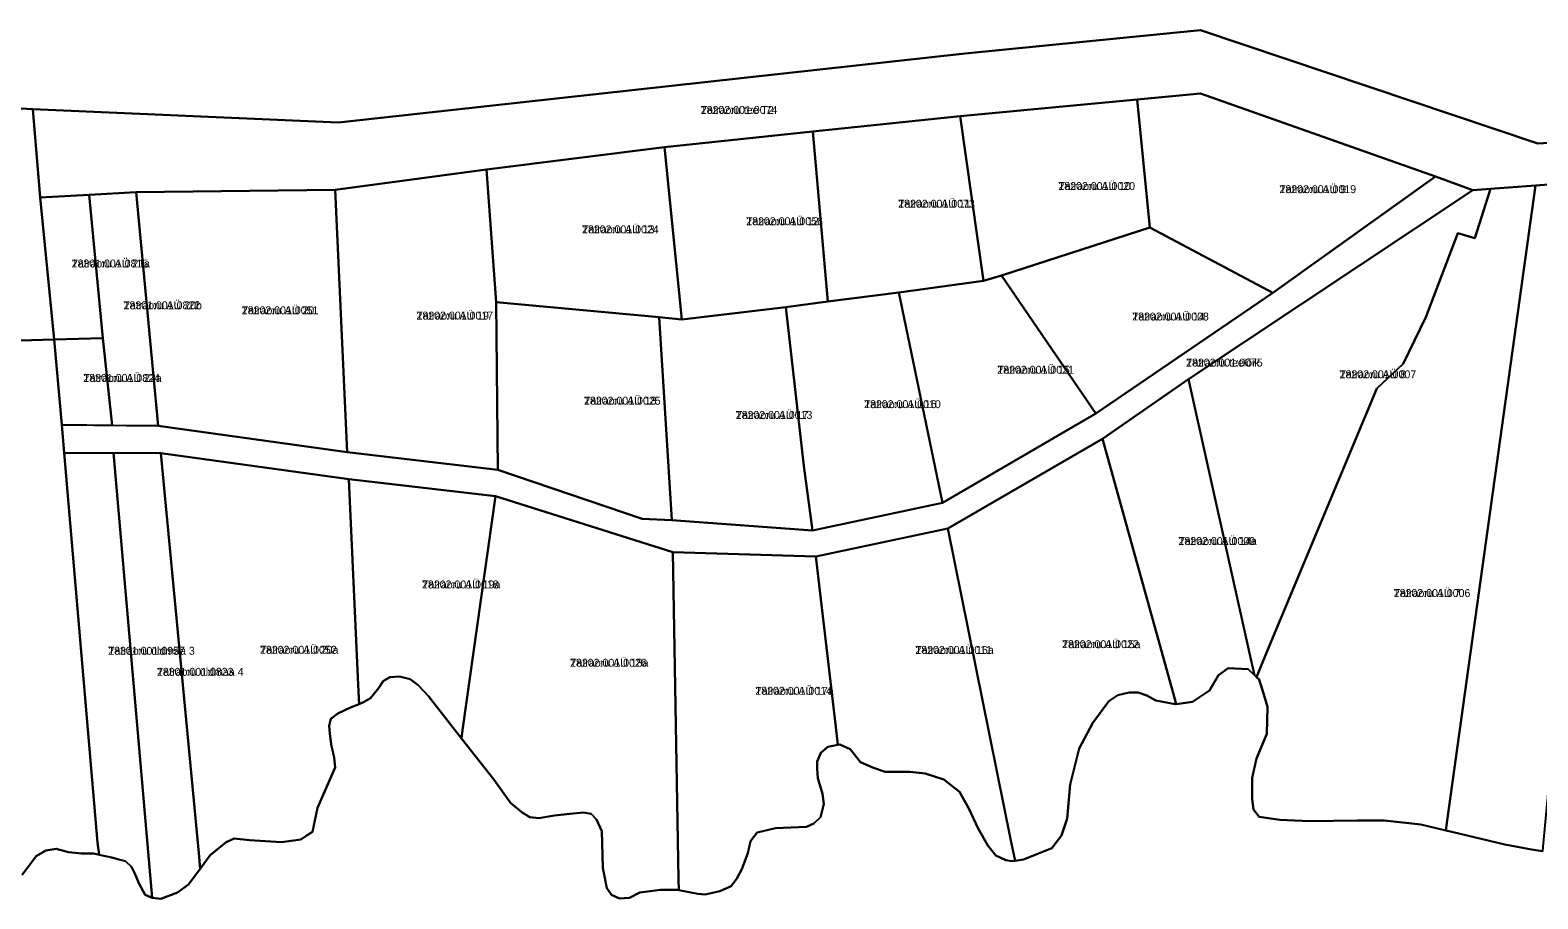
# Model space of a CAD drawing. Extents: x 647845 to 668483, y 6445298 to 6473683.
# Drawn here: x 655354.6 to 655639.8, y 6459755.9 to 6459920.2 of the extents above; entities that cross this region are included whole.
import ezdxf

# ---------------------------------------------------------------- set-up
doc = ezdxf.new("R2010")
doc.units = 0
for name, color, linetype in [('L_AADRESS', 7, 'Continuous'), ('PIIR', 7, 'Continuous'), ('TUNNUS', 7, 'Continuous')]:
    doc.layers.add(name, color=color, linetype=linetype)

msp = doc.modelspace()

# ---------------------------------------------------------------- linework, layer by layer
at = {"layer": 'PIIR'}
for points in [[(655768.57, 6459906.32), (655639.81, 6459898.78), (655575.98, 6459920.24), (655531.44, 6459915.82), (655412.9, 6459902.78), (655355.04, 6459905.27), (655320.6, 6459907.21)], [(655654.46, 6459891.98), (655639.35, 6459890.87), (655630.86, 6459890.25), (655627.53, 6459889.99), (655620.48, 6459892.55), (655576, 6459908.29), (655564.03, 6459907.15), (655530.51, 6459903.96), (655502.65, 6459901.05), (655474.56, 6459898.1), (655440.88, 6459893.86), (655412.27, 6459890.06), (655374.61, 6459889.57), (655365.71, 6459889.08), (655356.48, 6459888.57), (655355.04, 6459905.27), (655412.9, 6459902.78), (655531.44, 6459915.82), (655575.98, 6459920.24), (655639.81, 6459898.78), (655768.57, 6459906.32)], [(655311.68, 6459860.34), (655359.12, 6459861.71), (655360.53, 6459845.6), (655360.99, 6459840.29), (655367.3, 6459766.59), (655367.63, 6459764.27), (655366.6, 6459764.5), (655364.26, 6459764.49), (655361.82, 6459764.75), (655359.5, 6459765.35), (655357.54, 6459765.06), (655355.71, 6459764), (655353.02, 6459760.45)], [(655353.02, 6459760.45), (655355.71, 6459764), (655357.54, 6459765.06), (655359.5, 6459765.35), (655361.82, 6459764.75), (655364.26, 6459764.49), (655366.6, 6459764.5), (655367.63, 6459764.27), (655370.02, 6459763.77), (655371.36, 6459763.38), (655372.59, 6459763.03), (655373.73, 6459761.95), (655374.3, 6459760.83), (655375.21, 6459758.73), (655376.31, 6459756.65), (655377.65, 6459756.08), (655379.25, 6459755.92), (655382.43, 6459757.14), (655384.51, 6459758.61), (655386.72, 6459761.6), (655388.62, 6459764.18), (655391.67, 6459766.62), (655393.18, 6459767.34), (655396.06, 6459767.05), (655402.11, 6459766.64), (655405.77, 6459767.14), (655406.96, 6459767.94), (655407.97, 6459768.61), (655408.95, 6459773.13), (655410.66, 6459777.17), (655412.24, 6459780.76), (655412.08, 6459782.67), (655411.51, 6459785.12), (655411.23, 6459787.22), (655411.15, 6459788.67), (655411.44, 6459789.97), (655412.74, 6459790.99), (655415.18, 6459792.1), (655416.81, 6459792.76), (655417.63, 6459793.1), (655418.94, 6459793.9), (655420.5, 6459795.85), (655421.37, 6459797.12), (655422.6, 6459797.84), (655424.42, 6459798), (655426.47, 6459797.48), (655427.96, 6459796.37), (655429.91, 6459794.27), (655436.16, 6459786.28), (655442.26, 6459778.5), (655445.44, 6459774.1), (655447.65, 6459772.26), (655449.1, 6459771.34), (655450.82, 6459771.17), (655453.76, 6459771.66), (655456.69, 6459772.03), (655459.26, 6459772.28), (655460.68, 6459772.01), (655461.71, 6459770.93), (655462.69, 6459768.73), (655462.93, 6459761.76), (655463.66, 6459757.97), (655464.53, 6459756.66), (655466.05, 6459756), (655467.95, 6459756.14), (655469.9, 6459757.12), (655473.82, 6459757.61), (655477, 6459757.61), (655477.27, 6459757.56), (655480.86, 6459756.87), (655482.25, 6459756.76), (655485.03, 6459757.34), (655487.18, 6459758.34), (655488.27, 6459759.79), (655489.23, 6459761.53), (655490.33, 6459764.59), (655490.82, 6459766.8), (655492.09, 6459768.46), (655495.56, 6459769.26), (655501.42, 6459769.53), (655502.81, 6459770.18), (655504.09, 6459771.4), (655504.7, 6459773.85), (655504.46, 6459775.8), (655503.6, 6459778.74), (655503.44, 6459780.51), (655503.48, 6459781.93), (655504.15, 6459783.56), (655505.5, 6459784.67), (655507.38, 6459785.04), (655507.73, 6459785.11), (655509.72, 6459784.25), (655511.67, 6459781.8), (655514.12, 6459780.7), (655516.32, 6459779.97), (655520.97, 6459779.97), (655523.9, 6459779.61), (655527.45, 6459778.51), (655530.39, 6459776.19), (655532.1, 6459773.13), (655533.93, 6459769.22), (655535.77, 6459766.04), (655537.24, 6459764.09), (655539.19, 6459763.23), (655540.27, 6459763.02), (655540.9, 6459763.12), (655542.51, 6459763.39), (655547.85, 6459765.52), (655549.71, 6459767.93), (655550.78, 6459771.13), (655551.31, 6459777.54), (655553.06, 6459784.38), (655555.6, 6459789.22), (655558.62, 6459793.31), (655560.36, 6459794.47), (655562.51, 6459794.97), (655564.22, 6459794.97), (655565.84, 6459794.36), (655567.52, 6459793.45), (655571.19, 6459792.72), (655571.41, 6459792.75), (655574.49, 6459793.21), (655577.67, 6459795.3), (655579.38, 6459798.23), (655581.22, 6459799.58), (655585.01, 6459799.34), (655586.18, 6459798.24), (655586.56, 6459797.88), (655587.09, 6459797.38), (655587.96, 6459794.57), (655588.68, 6459792.25), (655588.56, 6459787.11), (655586.6, 6459782.46), (655585.75, 6459778.79), (655585.75, 6459774.75), (655586.01, 6459772.81), (655587.09, 6459771.45), (655591.01, 6459770.84), (655596.63, 6459770.6), (655605.68, 6459770.73), (655610.82, 6459770.73), (655617.67, 6459770.01), (655622.42, 6459768.87), (655623.78, 6459768.54), (655633.57, 6459766.23), (655638.64, 6459765.23), (655640.72, 6459764.95)]]:
    msp.add_lwpolyline(points, dxfattribs=at)
for points in [[(655356.48, 6459888.57), (655359.12, 6459861.71), (655311.68, 6459860.34), (655309.48, 6459884.36), (655283.02, 6459882.57), (655286.95, 6459909.12), (655320.6, 6459907.21), (655355.04, 6459905.27)], [(655566.42, 6459882.91), (655538.32, 6459873.83), (655534.92, 6459872.85), (655530.51, 6459903.96), (655564.03, 6459907.15)], [(655589.65, 6459870.53), (655566.42, 6459882.91), (655564.03, 6459907.15), (655576, 6459908.29), (655620.48, 6459892.55)], [(655530.51, 6459903.96), (655534.92, 6459872.85), (655518.92, 6459870.61), (655505.51, 6459868.92), (655502.65, 6459901.05)], [(655502.65, 6459901.05), (655505.51, 6459868.92), (655497.53, 6459867.87), (655477.84, 6459865.52), (655474.56, 6459898.1)], [(655474.56, 6459898.1), (655477.84, 6459865.52), (655473.54, 6459865.92), (655442.72, 6459868.8), (655440.88, 6459893.86)], [(655360.56, 6459845.6), (655378.76, 6459845.37), (655414.56, 6459840.41), (655443.03, 6459837.1), (655470.38, 6459827.8), (655475.98, 6459827.52), (655502.56, 6459825.62), (655527.17, 6459830.85), (655556.16, 6459847.73), (655589.65, 6459870.53), (655620.48, 6459892.55), (655627.53, 6459889.99), (655573.74, 6459854.22), (655557.45, 6459842.92), (655528.19, 6459825.96), (655503.19, 6459820.66), (655476.13, 6459821.49), (655442.58, 6459832.09), (655414.83, 6459835.32), (655379.28, 6459840.23), (655360.99, 6459840.29)], [(655440.88, 6459893.86), (655442.72, 6459868.8), (655443.03, 6459837.1), (655414.56, 6459840.41), (655412.27, 6459890.06)], [(655365.71, 6459889.08), (655374.61, 6459889.57), (655378.76, 6459845.37), (655370.09, 6459845.48), (655368.32, 6459861.95)], [(655412.27, 6459890.06), (655414.56, 6459840.41), (655378.76, 6459845.37), (655374.61, 6459889.57)], [(655627.88, 6459880.88), (655624.67, 6459881.81), (655618.62, 6459865.96), (655614.31, 6459857.14), (655609.35, 6459852.46), (655588.74, 6459803.1), (655586.56, 6459797.88), (655586.18, 6459798.24), (655585.26, 6459802.38), (655573.74, 6459854.22), (655627.53, 6459889.99), (655630.86, 6459890.25)], [(655622.68, 6459770.73), (655622.42, 6459768.87), (655617.67, 6459770.01), (655610.82, 6459770.73), (655605.68, 6459770.73), (655596.63, 6459770.6), (655591.01, 6459770.84), (655587.09, 6459771.45), (655586.01, 6459772.81), (655585.75, 6459774.75), (655585.75, 6459778.79), (655586.6, 6459782.46), (655588.56, 6459787.11), (655588.68, 6459792.25), (655587.96, 6459794.57), (655587.09, 6459797.38), (655586.56, 6459797.88), (655588.74, 6459803.1), (655609.35, 6459852.46), (655614.31, 6459857.14), (655618.62, 6459865.96), (655624.67, 6459881.81), (655627.88, 6459880.88), (655630.86, 6459890.25), (655639.35, 6459890.87)], [(655658.06, 6459850.82), (655653.33, 6459801.58), (655644.06, 6459800.68), (655640.79, 6459765.73), (655640.72, 6459764.95), (655638.64, 6459765.23), (655633.57, 6459766.23), (655623.78, 6459768.54), (655622.42, 6459768.87), (655622.68, 6459770.73), (655639.35, 6459890.87), (655654.46, 6459891.98)], [(655356.48, 6459888.57), (655365.71, 6459889.08), (655368.32, 6459861.95), (655359.12, 6459861.71)], [(655556.16, 6459847.73), (655538.32, 6459873.83), (655566.42, 6459882.91), (655589.65, 6459870.53)], [(655538.32, 6459873.83), (655556.16, 6459847.73), (655527.17, 6459830.85), (655518.92, 6459870.61), (655534.92, 6459872.85)], [(655502.56, 6459825.62), (655500.95, 6459837.8), (655497.53, 6459867.87), (655505.51, 6459868.92), (655518.92, 6459870.61), (655527.17, 6459830.85)], [(655473.54, 6459865.92), (655475.98, 6459827.52), (655470.38, 6459827.8), (655443.03, 6459837.1), (655442.72, 6459868.8)], [(655475.98, 6459827.52), (655473.54, 6459865.92), (655477.84, 6459865.52), (655497.53, 6459867.87), (655500.95, 6459837.8), (655502.56, 6459825.62)], [(655359.12, 6459861.71), (655368.32, 6459861.95), (655370.09, 6459845.48), (655360.56, 6459845.6)], [(655585.26, 6459802.38), (655586.18, 6459798.24), (655585.01, 6459799.34), (655581.22, 6459799.58), (655579.38, 6459798.23), (655577.67, 6459795.3), (655574.49, 6459793.21), (655571.41, 6459792.75), (655570.88, 6459794.65), (655557.45, 6459842.92), (655573.74, 6459854.22)], [(655557.45, 6459842.92), (655570.88, 6459794.65), (655571.41, 6459792.75), (655571.19, 6459792.72), (655567.52, 6459793.45), (655565.84, 6459794.36), (655564.22, 6459794.97), (655562.51, 6459794.97), (655560.36, 6459794.47), (655558.62, 6459793.31), (655555.6, 6459789.22), (655553.06, 6459784.38), (655551.31, 6459777.54), (655550.78, 6459771.13), (655549.71, 6459767.93), (655547.85, 6459765.52), (655542.51, 6459763.39), (655540.9, 6459763.12), (655540.06, 6459767.28), (655528.19, 6459825.96)], [(655360.99, 6459840.29), (655370.35, 6459840.26), (655377.65, 6459756.08), (655376.31, 6459756.65), (655375.21, 6459758.73), (655374.3, 6459760.83), (655373.73, 6459761.95), (655372.59, 6459763.03), (655371.36, 6459763.38), (655370.02, 6459763.77), (655367.63, 6459764.27), (655367.3, 6459766.59)], [(655379.28, 6459840.23), (655386.44, 6459764.54), (655386.72, 6459761.6), (655384.51, 6459758.61), (655382.43, 6459757.14), (655379.25, 6459755.92), (655377.65, 6459756.08), (655370.35, 6459840.26)], [(655416.64, 6459796.42), (655416.81, 6459792.76), (655415.18, 6459792.1), (655412.74, 6459790.99), (655411.44, 6459789.97), (655411.15, 6459788.67), (655411.23, 6459787.22), (655411.51, 6459785.12), (655412.08, 6459782.67), (655412.24, 6459780.76), (655410.66, 6459777.17), (655408.95, 6459773.13), (655407.97, 6459768.61), (655406.96, 6459767.94), (655405.77, 6459767.14), (655402.11, 6459766.64), (655396.06, 6459767.05), (655393.18, 6459767.34), (655391.67, 6459766.62), (655388.62, 6459764.18), (655386.72, 6459761.6), (655386.44, 6459764.54), (655379.28, 6459840.23), (655414.83, 6459835.32)], [(655436.38, 6459787.84), (655436.16, 6459786.28), (655429.91, 6459794.27), (655427.96, 6459796.37), (655426.47, 6459797.48), (655424.42, 6459798), (655422.6, 6459797.84), (655421.37, 6459797.12), (655420.5, 6459795.85), (655418.94, 6459793.9), (655417.63, 6459793.1), (655416.81, 6459792.76), (655416.64, 6459796.42), (655414.83, 6459835.32), (655442.58, 6459832.09)], [(655476.13, 6459821.49), (655477.23, 6459759.66), (655477.27, 6459757.56), (655477, 6459757.61), (655473.82, 6459757.61), (655469.9, 6459757.12), (655467.95, 6459756.14), (655466.05, 6459756), (655464.53, 6459756.66), (655463.66, 6459757.97), (655462.93, 6459761.76), (655462.69, 6459768.73), (655461.71, 6459770.93), (655460.68, 6459772.01), (655459.26, 6459772.28), (655456.69, 6459772.03), (655453.76, 6459771.66), (655450.82, 6459771.17), (655449.1, 6459771.34), (655447.65, 6459772.26), (655445.44, 6459774.1), (655442.26, 6459778.5), (655436.16, 6459786.28), (655436.38, 6459787.84), (655442.58, 6459832.09)], [(655528.19, 6459825.96), (655540.06, 6459767.28), (655540.9, 6459763.12), (655540.27, 6459763.02), (655539.19, 6459763.23), (655537.24, 6459764.09), (655535.77, 6459766.04), (655533.93, 6459769.22), (655532.1, 6459773.13), (655530.39, 6459776.19), (655527.45, 6459778.51), (655523.9, 6459779.61), (655520.97, 6459779.97), (655516.32, 6459779.97), (655514.12, 6459780.7), (655511.67, 6459781.8), (655509.72, 6459784.25), (655507.73, 6459785.11), (655507.38, 6459785.04), (655506.91, 6459788.95), (655503.19, 6459820.66)], [(655506.91, 6459788.95), (655507.38, 6459785.04), (655505.5, 6459784.67), (655504.15, 6459783.56), (655503.48, 6459781.93), (655503.44, 6459780.51), (655503.6, 6459778.74), (655504.46, 6459775.8), (655504.7, 6459773.85), (655504.09, 6459771.4), (655502.81, 6459770.18), (655501.42, 6459769.53), (655495.56, 6459769.26), (655492.09, 6459768.46), (655490.82, 6459766.8), (655490.33, 6459764.59), (655489.23, 6459761.53), (655488.27, 6459759.79), (655487.18, 6459758.34), (655485.03, 6459757.34), (655482.25, 6459756.76), (655480.86, 6459756.87), (655477.27, 6459757.56), (655477.23, 6459759.66), (655476.13, 6459821.49), (655503.19, 6459820.66)]]:
    msp.add_lwpolyline(points, close=True, dxfattribs=at)

# ---------------------------------------------------------------- texts
at = {"layer": 'L_AADRESS'}
for s, p in [('Tatraoru tee T2', (655481.43, 6459904.4)), ('Tatraoru AÜ 10', (655549.1, 6459890)), ('Tatraoru AÜ 9', (655590.93, 6459889.41)), ('Tatraoru AÜ 11', (655518.79, 6459886.66)), ('Tatraoru AÜ 12', (655490.04, 6459883.35)), ('Tatraoru AÜ 13', (655458.98, 6459881.81)), ('Tatraoru AÜ 21a', (655362.4, 6459875.35)), ('Tatraoru AÜ 20b', (655372.23, 6459867.45)), ('Tatraoru AÜ 20', (655394.59, 6459866.5)), ('Tatraoru AÜ 19', (655427.65, 6459865.5)), ('Tatraoru AÜ 14', (655563.07, 6459865.32)), ('Tatraoru teelõik', (655573.26, 6459856.61)), ('Tatraoru AÜ 22a', (655364.61, 6459853.7)), ('Tatraoru AÜ 15', (655537.54, 6459855.25)), ('Tatraoru AÜ 8', (655602.3, 6459854.39)), ('Tatraoru AÜ 18', (655459.35, 6459849.4)), ('Tatraoru AÜ 16', (655512.35, 6459848.74)), ('Tatraoru AÜ 17', (655488.05, 6459846.7)), ('Tatraoru AÜ 14a', (655571.82, 6459822.85)), ('Tatraoru AÜ 19a', (655428.7, 6459814.64)), ('Tatraoru AÜ 7', (655612.55, 6459813.01)), ('Tatraoru AÜ 20a', (655398.05, 6459802.28)), ('Tatraoru AÜ 16a', (655522.04, 6459802.25)), ('Tatraoru AÜ 15a', (655549.8, 6459803.34)), ('Tatraoru üldmaa 3', (655369.32, 6459802.09)), ('Tatraoru AÜ 18a', (655456.71, 6459799.83)), ('Tatraoru üldmaa 4', (655378.54, 6459798.11)), ('Tatraoru AÜ 17a', (655491.76, 6459794.52))]:
    msp.add_text(s, height=1.5, dxfattribs=at).set_placement(p)
at = {"layer": 'TUNNUS'}
for s, p in [('28202:001:0074', (655481.43, 6459904.4)), ('28202:001:0020', (655549.1, 6459890)), ('28202:001:0019', (655590.93, 6459889.41)), ('28202:001:0073', (655518.79, 6459886.66)), ('28202:001:0056', (655490.04, 6459883.35)), ('28202:001:0024', (655458.98, 6459881.81)), ('28301:001:0815', (655362.4, 6459875.35)), ('28301:001:0822', (655372.23, 6459867.45)), ('28202:001:0051', (655394.59, 6459866.5)), ('28202:001:0017', (655427.65, 6459865.5)), ('28202:001:0008', (655563.07, 6459865.32)), ('28202:001:0021', (655537.54, 6459855.25)), ('28202:001:0075', (655573.26, 6459856.61)), ('28202:001:0007', (655602.3, 6459854.39)), ('28301:001:0824', (655364.61, 6459853.7)), ('28202:001:0025', (655459.35, 6459849.4)), ('28202:001:0010', (655512.35, 6459848.74)), ('28202:001:0013', (655488.05, 6459846.7)), ('28202:001:0009', (655571.82, 6459822.85)), ('28202:001:0018', (655428.7, 6459814.64)), ('28202:001:0006', (655612.55, 6459813.01)), ('28202:001:0022', (655549.8, 6459803.34)), ('28301:001:0957', (655369.32, 6459802.09)), ('28202:001:0052', (655398.05, 6459802.28)), ('28202:001:0026', (655456.71, 6459799.83)), ('28202:001:0011', (655522.04, 6459802.25)), ('28301:001:0823', (655378.54, 6459798.11)), ('28202:001:0014', (655491.76, 6459794.52))]:
    msp.add_text(s, height=1.5, dxfattribs=at).set_placement(p)

doc.saveas('drawing.dxf')
